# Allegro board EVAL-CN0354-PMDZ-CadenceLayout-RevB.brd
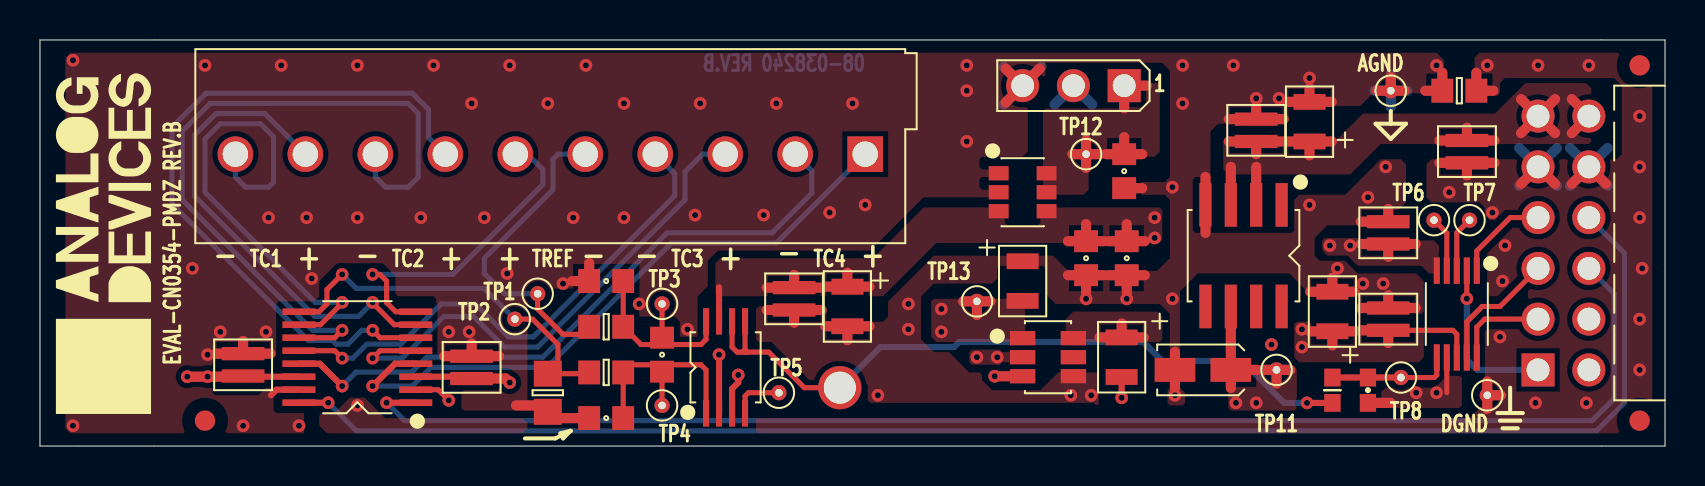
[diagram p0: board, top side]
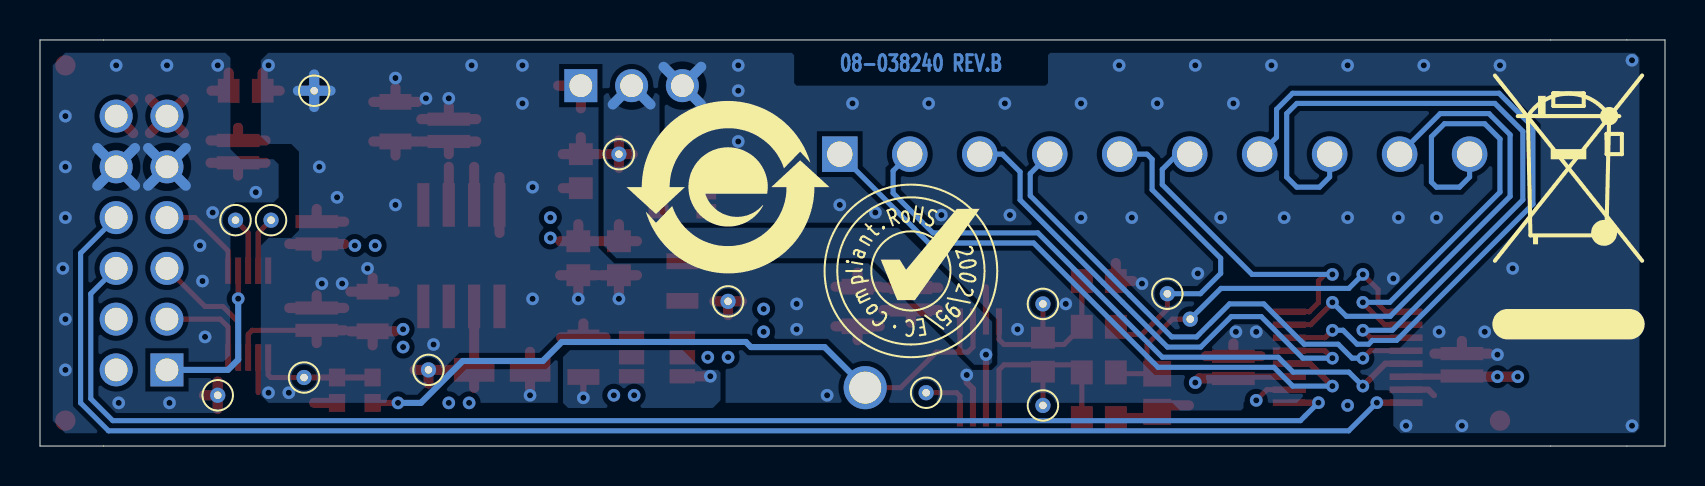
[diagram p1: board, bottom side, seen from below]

Outline 81.28 x 20.32 mm; copper layers: TOP, L2_GND, L3_PWR, BOTTOM. Coordinates in mm from the lower left corner of the outline.
Outline path: 0,20.32 0,0 81.28,0 81.28,20.32 0,20.32

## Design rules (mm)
net group ADD: nets A0 A1
net group D_A_B: nets UNNAMED_2_ADG709_I95_DA UNNAMED_2_ADG709_I95_DB
net group S1_A_B: nets UNNAMED_2_ADG709_I95_S1A UNNAMED_2_ADG709_I95_S1B
net group S2_A_B: nets UNNAMED_2_ADG709_I95_S2A UNNAMED_2_ADG709_I95_S2B
net group S3_A_B: nets UNNAMED_2_ADG709_I95_S3A UNNAMED_2_ADG709_I95_S3B
net group S4_A_B: nets UNNAMED_2_ADG709_I95_S4A UNNAMED_2_ADG709_I95_S4B

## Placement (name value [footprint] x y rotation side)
AGND  TESTPAD  [TPC30D15]  67.56 17.78 0 top
C1  1UF  [C0603]  31.12 4.57 270 top
C2  0.01uF  [C0603]  28.32 8.26 0 top
C3  0.01uF  [C0603]  28.32 1.4 180 top
C4  0.1uF  [C0508H28]  67.44 6.35 90 top
C5  10uF  [CPL0805]  64.64 6.73 90 top
C6  0.1uF  [C0508H28]  10.16 4.06 90 top
C7  0.1uF  [C0508H28]  21.59 3.94 90 top
C8  0.1uF  [C0508H28]  37.72 7.37 270 top
C9  10uF  [CPL0805]  40.39 6.99 270 top
C10  0.1uF  [C0508H28]  71.37 14.73 270 top
C11  0.1uF  [C0508H28]  60.83 15.8 90 top
C12  0.1uF  [C0603]  52.32 9.4 270 top
C13  0.1uF  [C0508H28]  67.44 10.67 90 top
C14  10uF  [CPL0805]  63.5 16.23 90 top
C15  1uF  [C0603]  54.36 9.4 270 top
C16  4.7uF  [CPL0805]  54.1 4.45 270 top
C17  4.7uF  [CPL0805]  49.15 8.26 270 top
C19  1UF  [C3216]  58.17 3.81 180 top
C20  0.1uF  [C0603]  54.23 13.75 270 top
C21  1000pF  [C0402]  66.42 2.79 270 top
DGND  TESTPAD  [TPC30D15]  72.39 2.54 0 top
NOREF  -  [unnamed]  80.01 19.05 0 top
NOREF#2  -  [#2]  -145.92 -230.5 0 top
NOREF#3  -  [#2]  0 20.32 270 top
NOREF#4  -  [#2]  78.11 0 0 top
NOREF#5  -  [#2]  -26.92 219.08 0 top
NOREF#6  -  [#2]  0 0 0 top
NOREF#7  -  [#2]  211.58 236.86 0 top
NOREF#8  -  [#2]  78.11 20.32 0 top
NOREF#9  -  [unnamed]  80.01 1.27 0 top
NOREF#10  -  [#2]  -153.54 -239.65 0 top
NOREF#11  -  [#2]  81.28 20.32 0 top
NOREF#12  -  [#2]  -154.81 -240.92 0 top
NOREF#13  -  [unnamed]  8.26 1.27 0 top
NOREF#14  -  [#2]  80.01 19.05 0 top
NOREF#15  -  [#2]  0 20.32 0 top
NOREF#16  -  [#2]  3.18 10.16 90 top
NOREF#17  -  [#2]  0 0 0 top
NOREF#18  -  [#2]  0 0 90 top
NOREF#19  -  [#2]  80.01 19.05 0 top
NOREF#20  -  [#2]  40.01 36.83 0 top
NOREF#21  -  [#2]  81.28 20.32 180 top
NOREF#22  -  [#2]  81.28 0 90 top
NOREF#23  -  [#2]  46.86 12.95 180 bottom
NOREF#24  -  [#2]  37.72 8.76 180 bottom
NOREF#25  -  [#2]  -4.44 22.23 180 bottom
P1  SAMTECTSW10608GS3PIN  [CNBERG1X3H205LD36]  54.23 18.03 180 top
P2  1984840  [CNPHOENIX1984840]  41.28 14.61 180 top
PMOD  TSW-106-25-F-D-RA  [CNHDRRA2X6H240]  74.93 3.81 90 top
R1  1MEG  [R0805]  25.4 2.67 270 top
R2  100  [R0603]  28.32 5.97 0 top
R3  100  [R0603]  28.32 3.68 0 top
R4  0  [R0603]  70.99 17.78 0 top
R8  1.1K  [R0402]  64.64 2.79 90 top
TP1  TESTPAD  [TPC30D15]  24.89 7.62 0 top
TP2  TESTPAD  [TPC30D15]  23.75 6.35 180 top
TP3  TESTPAD  [TPC30D15]  31.12 7.11 0 top
TP4  TESTPAD  [TPC30D15]  31.12 2.03 0 top
TP5  TESTPAD  [TPC30D15]  36.96 2.67 0 top
TP6  TESTPAD  [TPC30D15]  69.72 11.3 0 top
TP7  TESTPAD  [TPC30D15]  71.5 11.3 0 top
TP8  TESTPAD  [TPC30D15]  68.07 3.43 0 top
TP11  TESTPAD  [TPC30D15]  61.85 3.81 90 top
TP12  TESTPAD  [TPC30D15]  52.32 14.61 0 top
TP13  TESTPAD  [TPC30D15]  46.86 7.24 270 top
U1  ADG1609BRUZ  [TSSOP16]  15.88 4.45 90 top
U2  ADM8829ARTZ  [SOT23_6]  50.42 4.45 270 top
U3  AD7787BRMZ  [RM10]  70.87 6.6 180 top
U4  AD8495BRMZ  [MSOP8]  34.29 3.94 0 top
U6  REF194ESZ  [SO8]  60.2 9.53 180 top
U7  ADR3412ARJZ  [SOT23_6-2]  49.15 12.7 270 top
VOUT  BLK  [CNLOOPTP]  40.01 2.92 0 top

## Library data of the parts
AGND DGND TP1-TP8 TP11-TP13 = NCTESTPAD: User Part Number: UPN; part number: NCTESTPAD_TH-TESTPAD,E013464,P/O PCB,NONE,SCD-013939,TPC30D15,N/A
C1 = CAP: Tolerance: 10; User Part Number: UPN; alternate symbols: (C0402H22_ALT,C0201-2,C0402_A,C0402_ALT); part number: CAP_SM-1UF,25V,10,E006992,C0603; tolerance: 10
C2 C3 = CAP: Tolerance: 5; User Part Number: UPN; alternate symbols: (C0402H22_ALT,C0201-2,C0402_A,C0402_ALT); part number: CAP_SM-0.01UF,50V,5,E019502,C0603; tolerance: 5
C4 C6-C8 C10 C11 C13 = CAP: Tolerance: 10; User Part Number: UPN; alternate symbols: (C0402H22_ALT,C0201-2,C0402_A,C0402_ALT); part number: CAP_SM-0.1UF,16V,10,E019851,C0508H28; tolerance: 10
C5 C9 C14 = CAPP: Tolerance: 20; User Part Number: UPN; part number: CAPP_SM-10UF,6.3V,20,E020901,CPL0805; tolerance: 20
C12 C20 = CAP: Tolerance: 10; User Part Number: UPN; alternate symbols: (C0402H22_ALT,C0201-2,C0402_A,C0402_ALT); part number: CAP_SM-0.1UF,16V,10,E011547,C0603; tolerance: 10
C15 = CAP: Tolerance: 10; User Part Number: UPN; alternate symbols: (C0402H22_ALT,C0201-2,C0402_A,C0402_ALT); part number: CAP_SM-1UF,16V,10,E020596,C0603; tolerance: 10
C16 C17 = CAPP: Tolerance: 20; User Part Number: UPN; part number: CAPP_SM-4.7UF,10V,20,E020900,CPL0805; tolerance: 20
C19 = CAPP: Tolerance: 10; User Part Number: UPN; part number: CAPP_SM-1UF,25V,10,E000684,C3216; tolerance: 10
C21 = CAP: Tolerance: 5; User Part Number: UPN; alternate symbols: (C0402H22_ALT,C0201-2,C0402_A,C0402_ALT); part number: CAP_SM-1000PF,25V,5,E017843,C0402; tolerance: 5
P1 = CN3P: User Part Number: UPN; part number: CN3P_TH-SAMTECTSW10608GS3PIN,E000812,CNBERG1X3H205LD36
P2 = CN10P: User Part Number: UPN; part number: CN10P_TH-1984840,E020104,CNPHOENIX1984840
PMOD = CN12P_V3: User Part Number: UPN; part number: CN12P_V3_TH-TSW-106-25-F-D-RA,E018495,CNHDRRA2X6H240
R1 = RES: Tolerance: 1; User Part Number: UPN; alternate symbols: (RRAD984L1500W75H520LD32;TO220H590_ALT;R0402_A;R0603_A,R0402_ALT); part number: RES_SM-1MEG,E018283,1/8W,1,R0805; tolerance: 1
R2 R3 = RES: Tolerance: 0.1; User Part Number: UPN; alternate symbols: (RRAD984L1500W75H520LD32;TO220H590_ALT;R0402_A;R0603_A,R0402_ALT); part number: RES_SM-100,E017864,1/16W,0.1,R0603; tolerance: 0.1
R4 = RES: Tolerance: 1; User Part Number: UPN; alternate symbols: (RRAD984L1500W75H520LD32;TO220H590_ALT;R0402_A;R0603_A,R0402_ALT); part number: RES_SM-0,E004207,1/16W,1,R0603; tolerance: 1
R8 = RES: Tolerance: 1; User Part Number: UPN; alternate symbols: (RRAD984L1500W75H520LD32;TO220H590_ALT;R0402_A;R0603_A,R0402_ALT); part number: RES_SM-1.1K,E019550,1/16W,1,R0402; tolerance: 1
U1 = ADG709: User Part Number: UPN; part number: ADG709_SM-ADG1609BRUZ,E016397,TSSOP16,N/A
U2 = ADM8829: User Part Number: UPN; part number: ADM8829_SM-ADM8829ARTZ,E017975,SOT23_6,N/A
U3 = AD7787: User Part Number: UPN; part number: AD7787_SM-AD7787BRMZ,E019918,RM10,N/A
U4 = AD8495_PRELIM: User Part Number: UPN; part number: AD8495_PRELIM_SM-AD8495BRMZ,E011883,MSOP8,N/A
U6 = REF19X: User Part Number: UPN; part number: REF19X_SM-REF194ESZ,E019993,SO8,N/A
U7 = ADR34XX: User Part Number: UPN; part number: ADR34XX_SM-ADR3412ARJZ,E015880,SOT23_6-2,N/A
VOUT = CNTP1P: User Part Number: UPN; alternate symbols: (CNBANANA_ALT); part number: CNTP1P_TH-BLK,E000948,CNLOOPTP

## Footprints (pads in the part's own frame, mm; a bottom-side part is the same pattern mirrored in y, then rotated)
C0402
  rect 0.889x0.813 smd: 1(-0.635,0) 2(0.635,0)
C0508H28
  rect 0.66x2.134 smd: 1(-0.559,0) 2(0.559,0)
C0603
  rect 1.092x1.194 smd: 1(-0.851,0) 2(0.851,0)
C3216
  rect 2.032x1.194 smd: N(1.397,0) P(-1.397,0)
CNBERG1X3H205LD36
  rect 1.651x1.651 hole 1.143: 1(0,0)
  round 1.651 hole 1.143: 2(2.54,0) 3(5.08,0)
CNHDRRA2X6H240
  rect 1.651x1.651 hole 1.143: 1(0,0)
  round 1.651 hole 1.143: 2(2.54,0) 3(5.08,0) 4(7.62,0) 5(10.16,0) 6(12.7,0) 7(0,-2.54) 8(2.54,-2.54) 9(5.08,-2.54) 10(7.62,-2.54) 11(10.16,-2.54) 12(12.7,-2.54)
CNLOOPTP
  round 2.159 hole 1.6: 1(0,0)
CNPHOENIX1984840
  rect 1.778x1.778 hole 1.27: 1(0,0)
  round 1.778 hole 1.27: 2(3.5,0) 3(7,0) 4(10.5,0) 5(14,0) 6(17.501,0) 7(21.001,0) 8(24.501,0) 9(28.001,0) 10(31.501,0)
CPL0805
  rect 0.787x1.6 smd: N(0.991,0) P(-0.991,0)
MSOP8
  rect 0.305x1.321 smd: 1(-0.975,-2.301) 2(-0.325,-2.301) 3(0.325,-2.301) 4(0.975,-2.301) 5(0.975,2.301) 6(0.325,2.301) 7(-0.325,2.301) 8(-0.975,2.301)
R0402
  rect 0.889x0.813 smd: 1(-0.635,0) 2(0.635,0)
R0603
  rect 1.092x1.194 smd: 1(-0.851,0) 2(0.851,0)
R0805
  rect 1.295x1.397 smd: 1(-0.953,0) 2(0.953,0)
RM10
  rect 0.305x1.321 smd: 1(-1.001,-2.172) 2(-0.5,-2.172) 3(0,-2.172) 4(0.5,-2.172) 5(1.001,-2.172) 6(1.001,2.172) 7(0.5,2.172) 8(0,2.172) 9(-0.5,2.172) 10(-1.001,2.172)
SO8
  rect 0.61x2.184 smd: 1(-1.905,-2.54) 2(-0.635,-2.54) 3(0.635,-2.54) 4(1.905,-2.54) 5(1.905,2.54) 6(0.635,2.54) 7(-0.635,2.54) 8(-1.905,2.54)
SOT23_6
  rect 0.711x1.27 smd: 1(-0.953,-1.27) 2(0,-1.27) 3(0.953,-1.27) 4(0.953,1.27) 5(0,1.27) 6(-0.953,1.27)
SOT23_6-2
  rect 0.711x0.991 smd: 1(-0.95,-1.199) 2(0,-1.199) 3(0.95,-1.199) 4(0.95,1.199) 5(0,1.199) 6(-0.95,1.199)
TPC30D15
  round 0.762 hole 0.381: 1(0,0)
TSSOP16
  rect 0.33x1.651 smd: 1(-2.276,-2.921) 2(-1.626,-2.921) 3(-0.975,-2.921) 4(-0.325,-2.921) 5(0.325,-2.921) 6(0.975,-2.921) 7(1.626,-2.921) 8(2.276,-2.921) 9(2.276,2.921) 10(1.626,2.921) 11(0.975,2.921) 12(0.325,2.921) 13(-0.325,2.921) 14(-0.975,2.921) 15(-1.626,2.921) 16(-2.276,2.921)
unnamed
  round 1.016 smd: (0,0)

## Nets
AGND: AGND.1(N1) C2.1(N1) C3.2(N2) C4.2(N2) C5.N(N2) C6.2(N2) C7.2(N2) C8.2(N2) C9.N(N2) C11.2(N2) C12.2(N2) C13.2(N2) C14.N(N2) C15.2(N2) C17.P(N1) C19.N(N2) C20.2(N2) C21.2(N2) P1.3(N3) R1.2(N2) R4.1(N1) U1.15(GND) U2.4(GND) U3.7(GND) U4.3(VS_NEG) U6.4(GND) U7.1(GND_FORCE) U7.2(GND_SENSE)
DGND: C10.2(N2) DGND.1(N1) PMOD.5(GND1) PMOD.11(GND2) R4.2(N2)
VCC_PMOD: C4.1(N1) C5.P(N1) C6.1(N1) C8.1(N1) C9.P(N1) C10.1(N1) C11.1(N1) C12.1(N1) C14.P(N1) C15.1(N1) PMOD.6(VCC1) PMOD.12(VCC2) U1.2(EN) U1.14(VDD) U2.2(IN) U3.8(VDD) U4.7(VS_POS) U6.2(VS) U6.3(SLEEP_N) U7.3(ENABLE) U7.4(VIN)
VSS: C7.1(N1) C17.N(N2) TP13.1(N1) U1.3(VSS) U2.1(OUT)
4_5VA: C13.1(N1) C19.P(N1) TP11.1(N1) U3.5(REFIN) U6.6(OUTPUT)
A0: PMOD.9(P9) U1.1(A0)
A1: PMOD.10(P10) U1.16(A1)
CS_N: PMOD.1(P1) U3.2(CS_N)
MISO: PMOD.3(P3) U3.9(DOUT/RDY_N)
MOSI: PMOD.2(P2) U3.10(DIN)
SCLK: PMOD.4(P4) U3.1(SCLK)
UNNAMED_2_AD7787_I27_AIN1: TP6.1(N1) U3.4(AIN1(-))
UNNAMED_2_AD7787_I27_AIN1_1: TP7.1(N1) U3.3(AIN1(+))
UNNAMED_2_AD7787_I27_AIN2: C21.1(N1) R8.2(N2) TP8.1(N1) U3.6(AIN2)
UNNAMED_2_AD8495PRELIM_I28_INNE: C1.2(N2) C3.1(N1) R3.2(N2) TP4.1(N1) U4.1(IN_NEG)
UNNAMED_2_AD8495PRELIM_I28_INPO: C1.1(N1) C2.2(N2) R2.2(N2) TP3.1(N1) U4.8(IN_POS)
UNNAMED_2_AD8495PRELIM_I28_NC: TP5.1(N1) U4.4(NC)
UNNAMED_2_AD8495PRELIM_I28_VOUT: R8.1(N1) U4.5(VSENSE) U4.6(VOUT) VOUT.1(N1)
UNNAMED_2_ADG709_I95_DA: P2.6(N6) U1.8(DA)
UNNAMED_2_ADG709_I95_DB: R1.1(N1) R3.1(N1) TP2.1(N1) U1.9(DB)
UNNAMED_2_ADG709_I95_S1A: P2.1(N1) U1.4(S1A)
UNNAMED_2_ADG709_I95_S1B: P2.2(N2) U1.13(S1B)
UNNAMED_2_ADG709_I95_S2A: P2.3(N3) U1.5(S2A)
UNNAMED_2_ADG709_I95_S2B: P2.4(N4) U1.12(S2B)
UNNAMED_2_ADG709_I95_S3A: P2.7(N7) U1.6(S3A)
UNNAMED_2_ADG709_I95_S3B: P2.8(N8) U1.11(S3B)
UNNAMED_2_ADG709_I95_S4A: P2.9(N9) U1.7(S4A)
UNNAMED_2_ADG709_I95_S4B: P2.10(N10) U1.10(S4B)
UNNAMED_2_ADM8829_I70_CAP: C16.P(N1) U2.6(CAP+)
UNNAMED_2_ADM8829_I70_CAP_1: C16.N(N2) U2.3(CAP-)
UNNAMED_2_ADR34XX_I40_VOUTFORCE: C20.1(N1) P1.1(N1) TP12.1(N1) U7.5(VOUT_SENSE) U7.6(VOUT_FORCE)
UNNAMED_2_CN10P_I97_N5: P2.5(N5) R2.1(N1) TP1.1(N1)
VREF: P1.2(N2) U4.2(REF)

Pads without a net: PMOD 7 8; U2 5; U6 1 5 7 8

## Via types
v1: diameter 0.635, hole 0.305, TOP to BOTTOM, 118 vias

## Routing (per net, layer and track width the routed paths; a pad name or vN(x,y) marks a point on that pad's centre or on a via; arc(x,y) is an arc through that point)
AGND: length 73.9
  TOP w0.254: U3.7 70.37,2.67
  TOP w0.305: U1.15 11.84,2.82 11.56,2.54 ; U4.3 34.62,2.87 34.93,3.18 v1(34.93,3.56)
  TOP w0.508: 48.3,17.18 P1.3 ; P1.3 48.3,18.88 ; P1.3 50,18.88 ; C9.N 41.49,5.99 ; C9.N 39.28,5.99 ; C9.N 40.39,5.29 ; C12.2 53.23,8.55 ; C12.2 52.32,7.69 ; C12.2 51.42,8.55 ; C5.N 64.64,8.42 ; C5.N 63.54,7.72 ; C5.N 65.75,7.72 ; 69.29,17.78 R4.1 70.14,18.68 ; 8.79,4.62 C6.2 ; C6.2 11.53,4.62 ; C6.2 10.16,5.26 ; 54.36,7.69 C15.2 ; C15.2 53.45,8.55 ; C15.2 55.26,8.55 ; 66.06,11.23 C13.2 67.44,11.86 ; C4.2 67.44,7.55 ; C4.2 66.06,6.91 ; C4.2 68.81,6.91 ; C21.2 67.56,2.16 ; C8.2 39.09,6.81 ; C8.2 36.34,6.81 ; C8.2 37.72,6.17 ; C11.2 60.83,17 ; C11.2 62.21,16.36 ; C11.2 59.46,16.36 ; C3.2 25.72,1.4 R1.2 25.08,2.03 23.81,2.03 ; AGND.1 68.25,17.78 ; AGND.1 67.56,18.47 ; AGND.1 66.88,17.78 ; C7.2 22.96,4.5 ; C7.2 21.59,5.13 ; C7.2 20.22,4.5 ; 58.29,13.46 58.29,10.67 ; 62.39,17.22 C14.N ; C14.N 64.61,17.22 ; C14.N 63.5,17.92 ; 27.47,9.16 C2.1 26.62,8.26 ; 56.77,4.71 C19.N 56.77,2.91 ; C20.2 55.13,12.9
  L2_GND w0.508: P1.3 50.09,18.98 ; P1.3 48.21,17.09 ; P1.3 50.09,17.09 ; P1.3 48.21,18.98 ; 66.75,17.78 AGND.1 ; AGND.1 67.56,16.96 ; AGND.1 68.38,17.78 ; AGND.1 67.56,18.6
  BOTTOM w0.508: 48.21,18.98 P1.3 ; P1.3 50.09,18.98 ; P1.3 48.21,17.09 ; 67.56,16.96 AGND.1 ; AGND.1 66.75,17.78 ; AGND.1 67.56,18.6 ; AGND.1 68.38,17.78
  vias: v1(1.65,19.3) v1(1.65,1.02) v1(7.62,8.89) v1(8.26,19.05) v1(8.38,4.57) v1(9.02,5.71) v1(10.16,1.02) v1(11.3,5.71) v1(11.43,11.43) v1(12.07,19.05) v1(12.95,1.02) v1(13.34,11.43) v1(13.59,8.38) v1(15.88,19.05) v1(15.88,11.43) v1(19.05,11.43) v1(19.69,19.05) v1(20.45,5.71) v1(21.46,5.71) v1(21.59,17.14) v1(22.23,11.43) v1(23.37,8.64) v1(23.5,19.05) v1(25.4,17.14) v1(26.16,8.13) v1(26.67,11.43) v1(27.31,19.05) v1(29.21,17.14) v1(29.21,11.43) v1(29.97,7.11) v1(32.39,5.84) v1(32.77,11.56) v1(33.02,17.14) v1(36.2,11.56) v1(36.83,17.14) v1(39.5,11.68) v1(40.64,17.14) v1(41.28,12.07) v1(41.91,2.54) v1(43.43,7.11) v1(43.43,5.84) v1(46.36,19.05) v1(46.36,17.78) v1(46.36,15.24) v1(51.56,2.54) v1(52.32,7.37) v1(52.58,2.54) v1(54.36,7.37) v1(56.64,12.95) v1(56.64,7.37) v1(56.77,2.54) v1(57.15,19.05) v1(57.15,17.14) v1(59.69,19.05) v1(60.83,17.4) v1(61.6,5.08) v1(61.98,17.4) v1(63.5,18.41) v1(63.5,12.07) v1(64.9,8.89) v1(66.17,8.13) v1(66.42,12.45) v1(67.18,8.13) v1(67.31,13.97) v1(68.83,2.67) v1(69.85,19.05) v1(69.85,2.67)
DGND: length 35.8
  TOP w0.508: 78.32,13.12 PMOD.11 76.62,13.12 ; DGND.1 72.39,3.23 ; DGND.1 73.08,2.54 ; DGND.1 72.39,1.85 ; 71.84,18.68 R4.2 72.7,17.78 ; 74.08,13.12 PMOD.5 75.78,13.12 ; C10.2 72.75,14.17 ; C10.2 71.37,13.54 ; C10.2 70,14.17
  L2_GND w0.508: 76.53,14.91 PMOD.11 ; PMOD.11 78.41,13.03 ; PMOD.11 76.53,13.03 ; PMOD.11 78.41,14.91 ; PMOD.5 75.87,13.03 ; PMOD.5 73.99,14.91 ; PMOD.5 75.87,14.91 ; PMOD.5 73.99,13.03 ; DGND.1 73.21,2.54 ; DGND.1 72.39,3.36 ; DGND.1 72.39,1.72
  BOTTOM w0.508: 76.53,14.91 PMOD.11 ; PMOD.11 78.41,14.91 ; PMOD.11 78.41,13.03 ; PMOD.11 76.53,13.03 ; PMOD.5 75.87,14.91 ; PMOD.5 73.99,14.91 ; PMOD.5 75.87,13.03 ; PMOD.5 73.99,13.03
  vias: v1(15.88,2.03) v1(70.48,12.7) v1(72.39,19.05) v1(72.64,11.68) v1(73.03,5.46) v1(73.15,8.26) v1(73.28,10.03) v1(74.8,2.16) v1(74.93,19.05) v1(77.34,2.16) v1(77.47,19.05) v1(80.01,16.51) v1(80.01,13.97) v1(80.01,11.43) v1(80.01,6.35) v1(80.01,3.81) v1(80.14,8.89)
VCC_PMOD: length 61.9
  TOP w0.254: U3.8 70.87,5.59 70.66,5.79 C4.1 ; U1.2 19.91,2.82 v1(20.45,2.29)
  TOP w0.305: 10.2,3.47 C6.1 10.12,3.47 10.2,3.47 ; 10.2,3.47 U1.14 ; U4.7 33.96,7.95
  TOP w0.508: 63.54,5.74 C5.P ; C5.P 65.75,5.74 ; C5.P 64.64,5.04 ; C10.1 71.37,15.93 ; C10.1 72.75,15.29 ; C10.1 70,15.29 ; v1(7.37,3.47) v1(8.38,3.47) 10.12,3.47 ; PMOD.6 75.78,15.66 ; PMOD.6 74.08,15.66 ; PMOD.6 74.08,17.36 ; PMOD.6 75.78,17.36 ; C15.1 55.26,10.25 ; C15.1 53.45,10.25 ; C15.1 54.36,11.1 ; 62.39,15.24 C14.P ; C14.P 63.5,14.54 ; C14.P 64.61,15.24 ; 60.83,14.6 C11.1 ; C11.1 59.46,15.24 ; C11.1 62.21,15.24 ; C8.1 37.72,8.56 ; C8.1 39.09,7.92 ; C8.1 36.34,7.92 ; U6.2 60.83,13.97 ; U6.3 59.56,13.97 ; C12.1 53.23,10.25 ; C12.1 52.32,11.1 ; C12.1 51.42,10.25 ; C9.P 41.49,7.98 ; C9.P 39.28,7.98 ; C9.P 40.39,8.68 ; 76.62,15.66 PMOD.12 76.62,17.36 ; 66.06,5.79 C4.1 67.44,5.15
  L3_PWR w0.508: 73.99,17.45 PMOD.6 ; PMOD.6 73.99,15.57 ; PMOD.6 75.87,17.45 ; PMOD.6 75.87,15.57 ; PMOD.12 78.41,17.45 ; PMOD.12 76.53,15.57 ; PMOD.12 78.41,15.57 ; PMOD.12 76.53,17.45
  vias: v1(46.86,4.45) v1(47.88,4.45) v1(55.75,11.43) v1(55.75,10.41) v1(63.12,5.84) v1(63.12,4.95)
VSS: length 6.9
  TOP w0.305: C7.1 21.5,3.47 U1.3
  TOP w0.508: TP13.1 47.55,7.24 ; TP13.1 46.86,6.55 ; TP13.1 46.17,7.24 ; v1(23.5,3.18) 23.29,3.38 C7.1
  vias: v1(45.09,6.86) v1(45.09,5.71)
4_5VA: length 13.3
  TOP w0.508: C13.1 68.81,10.11 ; C13.1 67.44,9.47 ; C13.1 66.06,10.11 ; 59.56,2.91 C19.P ; C19.P 59.56,6.99 ; C19.P 60.89,3.81 ; TP11.1 62.54,3.81 ; TP11.1 61.85,3.12 ; TP11.1 61.16,3.81
  L3_PWR w0.508: 61.85,2.99 TP11.1 ; TP11.1 62.66,3.81 ; TP11.1 61.03,3.81
  vias: v1(59.82,2.16) v1(60.83,2.16) v1(64.52,10.03) v1(65.53,10.03)
A0: length 70.7
  TOP w0.305: U1.1 v1(17.34,2.17)
  BOTTOM w0.254: PMOD.9 78.74,7.62 78.74,2.37 77.64,1.27 18.23,1.27 18.01,1.5 v1(17.34,2.17)
A1: length 77.5
  TOP w0.305: U1.16 v1(14.41,2.17)
  BOTTOM w0.254: PMOD.10 79.25,9.65 79.25,2.16 77.85,0.76 15.82,0.76 v1(14.41,2.17)
CS_N: length 8.2
  TOP w0.254: U3.2 v1(71.37,7.37)
  BOTTOM w0.305: v1(71.37,7.37) 71.37,4.33 71.88,3.81 PMOD.1
MISO: length 6.5
  TOP w0.254: PMOD.3 73.03,6.99 72.14,6.99 71.37,6.22 U3.9
MOSI: length 4.7
  TOP w0.254: U3.10 71.87,5.95 72.26,6.35 PMOD.2
SCLK: length 4.7
  TOP w0.254: U3.1 71.87,9.76 73.53,11.43 PMOD.4
UNNAMED_2_AD7787_I27_AIN1: length 2.8
  TOP w0.254: U3.4 70.37,10.66 TP6.1
UNNAMED_2_AD7787_I27_AIN1_1: length 2.8
  TOP w0.254: TP7.1 70.87,10.67 U3.3
UNNAMED_2_AD7787_I27_AIN2: length 6.2
  TOP w0.254: TP8.1 69.74,3.43 69.87,3.56 U3.6
  TOP w0.305: R8.2 C21.1 TP8.1
UNNAMED_2_AD8495PRELIM_I28_INNE: length 10.8
  TOP w0.254: C1.2 30.77,4.06 29.55,4.06 R3.2 C3.1 ; C1.2 TP4.1 ; C1.2 31.46,4.06 33.06,4.06 33.31,3.81 U4.1
UNNAMED_2_AD8495PRELIM_I28_INPO: length 9.8
  TOP w0.254: C1.1 TP3.1 ; C1.1 30.77,5.08 30.06,5.08 R2.2 C2.2 ; C1.1 31.46,5.08 33.06,5.08 33.31,5.33 U4.8
UNNAMED_2_AD8495PRELIM_I28_NC: length 2.6
  TOP w0.254: TP5.1 35.43,2.67 35.27,2.5 U4.4
UNNAMED_2_AD8495PRELIM_I28_VOUT: length 36.3
  TOP w0.254: 35.14,4.7 35.27,4.7 ; 35.14,4.7 35.27,4.83 ; 35.14,4.7 34.87,4.7 34.62,4.95 U4.6 ; 35.27,4.7 35.39,4.7 ; 35.27,4.7 35.27,4.83 ; 35.39,4.7 35.27,4.83 ; 35.39,4.7 36.45,4.7 38.23,2.92 VOUT.1 ; 35.27,4.83 U4.5
  TOP w0.305: R8.1 v1(63.37,2.16)
  BOTTOM w0.305: v1(63.37,2.16) 62.23,2.16 60.13,4.25 56.13,4.25 55.18,5.21 45.97,5.21 45.72,4.95 42.04,4.95 VOUT.1
UNNAMED_2_ADG709_I95_DA: length 16.4
  TOP w0.254: U1.8 17.79,6.72 17.34,7.18 17.34,8.26 17,8.59 v1(16.64,8.59)
  BOTTOM w0.254: v1(16.64,8.59) 20.65,8.59 25.15,13.08 25.15,13.84 24.38,14.61 P2.6
UNNAMED_2_ADG709_I95_DB: length 19.4
  TOP w0.254: U1.9 13.96,6.72 14.35,7.11 14.35,7.83 v1(15.11,8.59) ; TP2.1 24.64,6.35 25.91,5.08 25.91,4.13 R1.1 27.41,3.62 R3.1
  BOTTOM w0.254: TP2.1 22.21,7.89 15.81,7.89 v1(15.11,8.59)
UNNAMED_2_ADG709_I95_S1A: length 32.1
  TOP w0.305: U1.4 17.76,4.12 v1(16.64,3)
  BOTTOM w0.254: P2.1 36.83,10.16 31.58,10.16 25.36,3.94 19.56,3.94 18.62,3 v1(16.64,3)
UNNAMED_2_ADG709_I95_S1B: length 32.4
  TOP w0.305: U1.13 13.99,4.12 v1(15.11,3)
  BOTTOM w0.254: P2.2 38.61,13.77 38.61,12.66 36.62,10.67 31.37,10.67 25.15,4.45 19.35,4.45 18.6,3.7 15.81,3.7 v1(15.11,3)
UNNAMED_2_ADG709_I95_S2A: length 26.3
  TOP w0.254: v1(16.64,4.4) 17.01,4.77 U1.5
  BOTTOM w0.254: v1(16.64,4.4) 18.11,4.4 20.19,6.48 21.7,6.48 23.22,4.95 24.89,4.95 27.13,7.2 28.1,8.16 32.26,12.32 32.26,13.72 33.15,14.61 P2.3
UNNAMED_2_ADG709_I95_S2B: length 26.2
  TOP w0.254: v1(15.11,4.4) 14.74,4.77 U1.12
  BOTTOM w0.254: v1(15.11,4.4) 15.65,4.4 16.35,5.1 18.05,5.1 20.07,7.11 21.78,7.11 23.43,5.46 24.68,5.46 26.77,7.56 27.74,8.52 31.75,12.53 31.75,13.63 P2.4
UNNAMED_2_ADG709_I95_S3A: length 35.8
  TOP w0.254: v1(16.64,5.79) 17.01,5.42 U1.6
  BOTTOM w0.254: P2.7 19.43,15.45 19.43,16.85 18.63,17.65 8.3,17.65 6.6,15.96 6.6,12.11 13.43,5.29 14.63,5.29 14.82,5.1 15.4,5.1 16.1,5.79 v1(16.64,5.79)
UNNAMED_2_ADG709_I95_S3B: length 35.9
  TOP w0.254: U1.11 14.74,5.42 v1(15.11,5.79)
  BOTTOM w0.254: P2.8 16.77,13.46 17.28,12.95 18.42,12.95 18.92,13.46 18.92,16.64 18.42,17.14 8.51,17.14 7.11,15.75 7.11,12.32 13.64,5.79 v1(15.11,5.79)
UNNAMED_2_ADG709_I95_S4A: length 24.2
  TOP w0.254: U1.7 17.72,6.07 16.64,7.16 v1(16.64,7.19)
  BOTTOM w0.254: v1(16.64,7.19) 15.94,6.49 13.74,6.49 7.75,12.49 7.75,15.58 8.81,16.64 11.24,16.64 P2.9
UNNAMED_2_ADG709_I95_S4B: length 24.1
  TOP w0.254: U1.10 14.03,6.07 15.11,7.16 v1(15.11,7.19)
  BOTTOM w0.254: v1(15.11,7.19) 13.77,7.19 8.26,12.7 8.26,15.37 9.02,16.13 11.03,16.13 11.68,15.48 11.68,13.21 11.43,12.95 10.28,12.95 9.77,13.46 P2.10
UNNAMED_2_ADM8829_I70_CAP: length 2.9
  TOP w0.508: 52.99,5.44 C16.P ; C16.P 54.1,6.14 ; C16.P 55.21,5.44
UNNAMED_2_ADM8829_I70_CAP_1: length 2.4
  TOP w0.305: C16.N v1(54.1,2.41)
  TOP w0.508: U2.3 v1(47.75,3.49)
UNNAMED_2_ADR34XX_I40_VOUTFORCE: length 7.7
  TOP w0.508: 51.64,14.61 TP12.1 ; TP12.1 52.32,13.92 ; TP12.1 52.32,15.29 ; TP12.1 53.01,14.61 ; 54.23,16.9 P1.1 55.36,18.03 ; C20.1 55.13,14.61 ; C20.1 54.23,15.46 ; C20.1 53.32,14.61
UNNAMED_2_CN10P_I97_N5: length 16
  TOP w0.254: TP1.1 24.89,6.86 26.16,5.59 27.09,5.59 R2.1
  BOTTOM w0.254: TP1.1 23.24,7.62 22.23,8.64 22.23,9.4 25.65,12.83 25.65,14.35 25.91,14.61 P2.5
VREF: length 5.6
  TOP w0.305: U4.2 v1(33.96,4.57)
  BOTTOM w0.508: 50.75,17.09 P1.2 52.63,17.09

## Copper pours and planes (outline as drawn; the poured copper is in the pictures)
AGND on TOP: 67.18,1.91 70.99,1.91 71.12,2.03 71.12,3.43 70.99,3.56 70.36,3.56 69.72,2.92 67.31,2.92 67.06,2.67 67.06,2.03
AGND on TOP: outline of 192 points within 1.27,0.64 70.23,19.69
AGND on BOTTOM: 1.28,0.89 1.28,19.43 1.52,19.67 30.74,19.67 30.86,19.56 30.86,18.16 30.99,18.03 43.43,18.03 43.56,18.16 43.56,19.56 43.68,19.67 69.86,19.67 70.23,19.3 70.23,15.49 69.85,15.11 68.71,15.11 68.33,14.73 68.33,10.79 68.71,10.41 69.85,10.41 70.23,10.03 70.23,2.54 69.85,2.16 24.64,2.16 24.26,1.78 21.21,1.78 21.08,1.91 21.08,2.16 18.42,2.16 17.78,2.79 13.84,2.79 13.59,2.54 13.59,1.02 13.22,0.65 1.52,0.65 ; 3 cut-outs
AGND on L2_GND: 1.28,0.89 1.28,19.43 1.52,19.67 61.85,19.67 61.86,19.69 69.85,19.69 70.23,19.3 70.23,15.49 69.85,15.11 68.71,15.11 68.33,14.73 68.33,10.79 68.71,10.41 69.85,10.41 70.23,10.03 70.23,2.54 69.85,2.16 18.42,2.16 17.78,2.79 13.84,2.79 13.59,2.54 13.59,1.02 13.22,0.65 1.52,0.65
DGND on TOP: 79.06,19.69 79.2,18.24 80.64,18.1 80.64,12.83 80.65,12.82 80.65,2.22 79.2,2.08 79.06,0.64 35.94,0.64 35.81,0.76 35.81,1.4 71.5,1.4 72.26,2.16 72.26,5.71 72.39,5.84 73.91,5.84 74.42,6.35 74.42,7.75 74.68,8 74.68,8.13 74.17,8.64 74.04,8.64 72.9,7.49 72.52,7.49 72.39,7.62 72.39,9.65 73.66,10.92 73.91,10.92 73.91,11.81 73.28,11.81 72.77,11.3 72.52,11.3 72.26,11.56 72.26,11.94 72.01,12.19 69.6,12.19 69.34,12.45 69.34,14.1 69.6,14.35 78.87,14.35 79.12,14.61 79.12,18.03 78.74,18.41 73.28,18.41 73.03,18.16 73.03,17.65 72.9,17.53 72.01,17.53 71.76,17.78 71.76,19.43 72.01,19.69
DGND on TOP: 13.97,1.02 13.97,1.52 14.1,1.65 14.73,1.65 15.49,2.41 16.26,2.41 17.27,1.4 24.13,1.4 24.38,1.14 24.38,0.89 24.13,0.64 14.35,0.64 13.97,1.02
DGND on BOTTOM: 71.76,4.57 71.76,11.94 71.5,12.19 69.6,12.19 69.34,12.45 69.34,14.1 69.6,14.35 71.25,14.35 71.76,14.86 71.76,19.43 71.76,19.43 72.01,19.68 80.01,19.68 80.64,19.05 80.64,1.27 80.01,0.64 72.77,0.64 72.27,1.14 72.26,1.14 72.26,4.06
DGND on L2_GND: 71.76,19.43 72.01,19.68 80.01,19.68 80.64,19.05 80.64,1.27 80.01,0.64 14.48,0.64 13.97,1.14 13.97,2.29 14.22,2.54 16.13,2.54 17.27,1.4 71.5,1.4 71.63,1.52 71.76,1.65 71.76,11.94 71.5,12.19 69.6,12.19 69.34,12.45 69.34,14.1 69.6,14.35 71.25,14.35 71.76,14.86
VCC_PMOD on TOP: 34.04,9.4 41.66,9.4 44.2,11.94 48.26,11.94 48.26,11.18 48.39,11.05 49.91,11.05 50.04,11.18 50.04,11.81 50.17,11.94 56.01,11.94 56.13,11.81 56.13,10.29 56.01,10.16 44.83,10.16 42.16,7.49 33.91,7.49 33.78,7.62 33.78,9.14
VCC_PMOD on TOP: 49.66,4.7 49.66,4.19 48.13,4.19 48.01,4.06 46.61,4.06 46.48,4.19 46.48,4.7 46.61,4.83 48.01,4.83 48.13,4.7
VCC_PMOD on TOP: 67.06,15.11 65.53,13.59 59.44,13.59 59.18,13.84 59.18,15.24 59.31,15.37 64.9,15.37 66.17,16.64 72.77,16.64 74.3,18.16 77.34,18.16 77.6,17.91 77.6,15.24 77.47,15.11
VCC_PMOD on TOP: 68.96,4.19 69.22,4.45 69.22,5.71 69.09,5.84 63.63,5.84 63.63,6.1 63.5,6.22 62.87,6.22 62.74,6.1 62.74,4.45 62.99,4.19
VCC_PMOD on L3_PWR: 54.74,19.68 80.01,19.68 80.64,19.05 80.64,5.08 80.65,5.07 80.65,1.27 80.01,0.64 72.64,0.64 71.76,1.52 71.76,12.32 71.37,12.7 63.88,12.7 63.5,12.32 63.5,4.83 63.25,4.57 58.29,4.57 58.29,1.52 57.4,0.64 1.27,0.64 1.27,19.69 54.73,19.69 ; 1 cut-out
VSS on TOP: 49.02,5.21 49.28,5.46 49.28,7.37 44.7,7.37 44.58,7.24 44.58,5.46 44.83,5.21
VSS on L3_PWR: 45.72,6.99 45.72,3.18 45.21,2.67 22.99,2.67 22.73,2.92 22.73,7.11 23.24,7.62 45.09,7.62
4_5VA on TOP: 69.98,8.76 69.98,10.03 69.72,10.29 66.04,10.29 65.91,10.41 64.26,10.41 64.14,10.29 64.14,9.78 64.39,9.53 65.41,9.53 65.91,9.02 69.09,9.02 69.47,8.64 69.85,8.64
4_5VA on TOP: 59.56,1.78 62.74,1.78 62.87,1.91 62.87,3.81 62.74,3.94 59.44,3.94 59.44,1.91
4_5VA on L3_PWR: 59.18,4.06 63.75,4.06 64.14,4.45 64.14,10.29 64.26,10.41 70.87,10.41 71.12,10.16 71.12,1.02 70.74,0.64 59.94,0.64 59.18,1.4
UNNAMED_2_ADM8829_I70_CAP on TOP: 51.69,6.73 55.88,6.73 56.13,6.48 56.13,5.33 56.01,5.21 51.56,5.21 51.31,5.46 51.31,6.35
UNNAMED_2_ADM8829_I70_CAP_1 on BOTTOM: 47.63,1.91 54.86,1.91 55.12,2.16 55.12,4.45 54.74,4.83 49.15,4.83 48.13,3.81 47.37,3.81 47.24,3.68 47.24,2.29
UNNAMED_2_ADR34XX_I40_VOUTFORCE on TOP: 53.98,16.89 54.1,17.02 54.1,18.03 54.23,18.16 55.88,18.16 56.01,18.03 56.01,14.73 55.75,14.48 52.45,14.48 52.45,12.83 52.2,12.57 50.29,12.57 50.17,12.7 50.17,16.76 50.29,16.89
VREF on BOTTOM: 38.35,10.92 33.66,6.22 33.66,4.19 33.78,4.06 34.54,4.06 35.18,4.7 35.18,4.83 39.75,9.4 52.45,9.4 53.09,10.03 53.09,17.53 52.96,17.65 50.42,17.65 50.29,17.53 50.29,11.68 49.53,10.92

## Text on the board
BOTTOM: 08-038240 REV.B
Ref Des/Silkscreen Top: TC1 | TC2 | TREF | TC3 | TC4 | EVAL-CN0354-PMDZ REV.B | - | +
PAGE_OUTLINE: E.ESGUERRA | APR14 | AUG13 | N/A | B | AS PER ECR NO.047281 | AUG14 | NOTES: | 1. THE BOARD SIZE MAY VARY TO COMPENSATE THE COMPONENTS DENSITY OF THE CIRCUIT. | 2. THE BOARD MAY EXTEND TO THE RIGHT AND LOWER PORTION IF THERE IS A NEED TO CHANGE THE BOARD SIZE. | 3. J1 CONNECTOR LOCATION IS FIXED WITH REFERENCE TO THE DISTANCE ON BOARD EDGE ON THE UPPER LEFT PORTION.
DIMENSION: (REF)
DISPLAY_BOTTOM: L2 GND | 08-      -07
User.6: L3 PWR | 08-      -08
User.7: ROHS COMPLIANCE NOTE: | 100 MICRO INCHES NICKEL/ | 3-5 MICRO INCHES GOLD | HOMOGENOUS MATERIALS IN THIS BOARD SHALL BE COMPLIANT | THE EU RoHS DIRECTIVE 2002/95/EC
User.23: FIGURE | SIZE | 12.0 | 15.0 | 45.0 | 50.0 | 63.0 | DRILL CHART: TOP to BOTTOM | ALL UNITS ARE IN MILS | TOLERANCE | +3.0/-3.0 | PLATED | QTY | 118 | 13 | 15 | 10 | 1
